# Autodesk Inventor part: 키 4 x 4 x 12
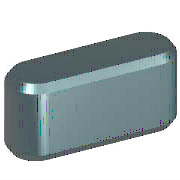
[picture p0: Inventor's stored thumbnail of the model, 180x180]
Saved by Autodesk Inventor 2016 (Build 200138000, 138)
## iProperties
IsCustomPart: 1
Created: 2012-02
Part Number: 키 4 x 4 x 12
Material: 강철, 연강
Description: 키 및 해당 키홈
Document SubType Name: Modeling
Standard: KS B 1311
Designer: mduedu
Standards Organization: KS
Language: ko-KR
Size Designation: 4 x 4 x 12
Categories: <MemberInstance><Categories><Category DisplayName="샤프트 부품" InternalName="7f7aeb1f-a693-4053-b835-cee3144e0d98" Mnemonic="SHFT"><Category DisplayName="키" Interna
Density: 1 g/cm^3
Appearance: 노란색
Author: mduedu
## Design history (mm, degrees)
workplane "Work Plane1"
workplane "Work Plane2"
sketch "스케치1"
  geometry: L1 (2, 2)-(10, 2); L2 (10, -2)-(2, -2); L3 (0, 9.4)-(0, -7.4) reference; L4 (-5, 0)-(30, 0) reference; L5 (12, 0)-(12, 7); A1 r 2 centre (2, 0) between (2, 2) and (2, -2); A2 r 2 centre (10, 0) between (10, -2) and (10, 2)
  constraints: 6 end point, 5 point on circle, 4 tangent, 3 point on line, 2 centre point, 1 horizontal, 1 parallel, 1 perpendicular
  dimensions: "d0" = 2 radius of A1 (= 0.5 x PB); "d13" = 2 radius of A2 (= 0.5 x PB); "d14" = 12 distance between parallel lines of L5 L3 (= NLG)
extrude "본체1" new body sketch "스케치1" taper "d3" = 0 deg; stored distance "d4" = 10
workplane "Work Plane3"
body "Solid1"
chamfer "모따기1" distance "d8" = 0.25 (= PHH); stored, may be unused: second distance "d9" = 0.25 (= PHH), angle "d15" = 45 deg
other parameters: "d1" = -2.5 (= -PNT), "d2" = 1.5 (= PH - PNT), "NLG" = 12 [user parameter; used in 3 equation terms], "PB" = 4 [user parameter; used in 2 equation terms], "PNT" = 2.5 [user parameter; used in 2 equation terms], "PH" = 4 [user parameter; used in 1 equation term], "PHH" = 0.25 [user parameter; used in 2 equation terms], "d10" = 0, "d16" = 0, "d17" = 0, "d18" = 0, "PLB2" = 12 (= NLG) [user parameter], "WDMAX" = 12 [user parameter], "PLB1" = 12 (= NLG) [user parameter], "RR" = 0.08 [user parameter], "PUEB" = 1.8 [user parameter]
